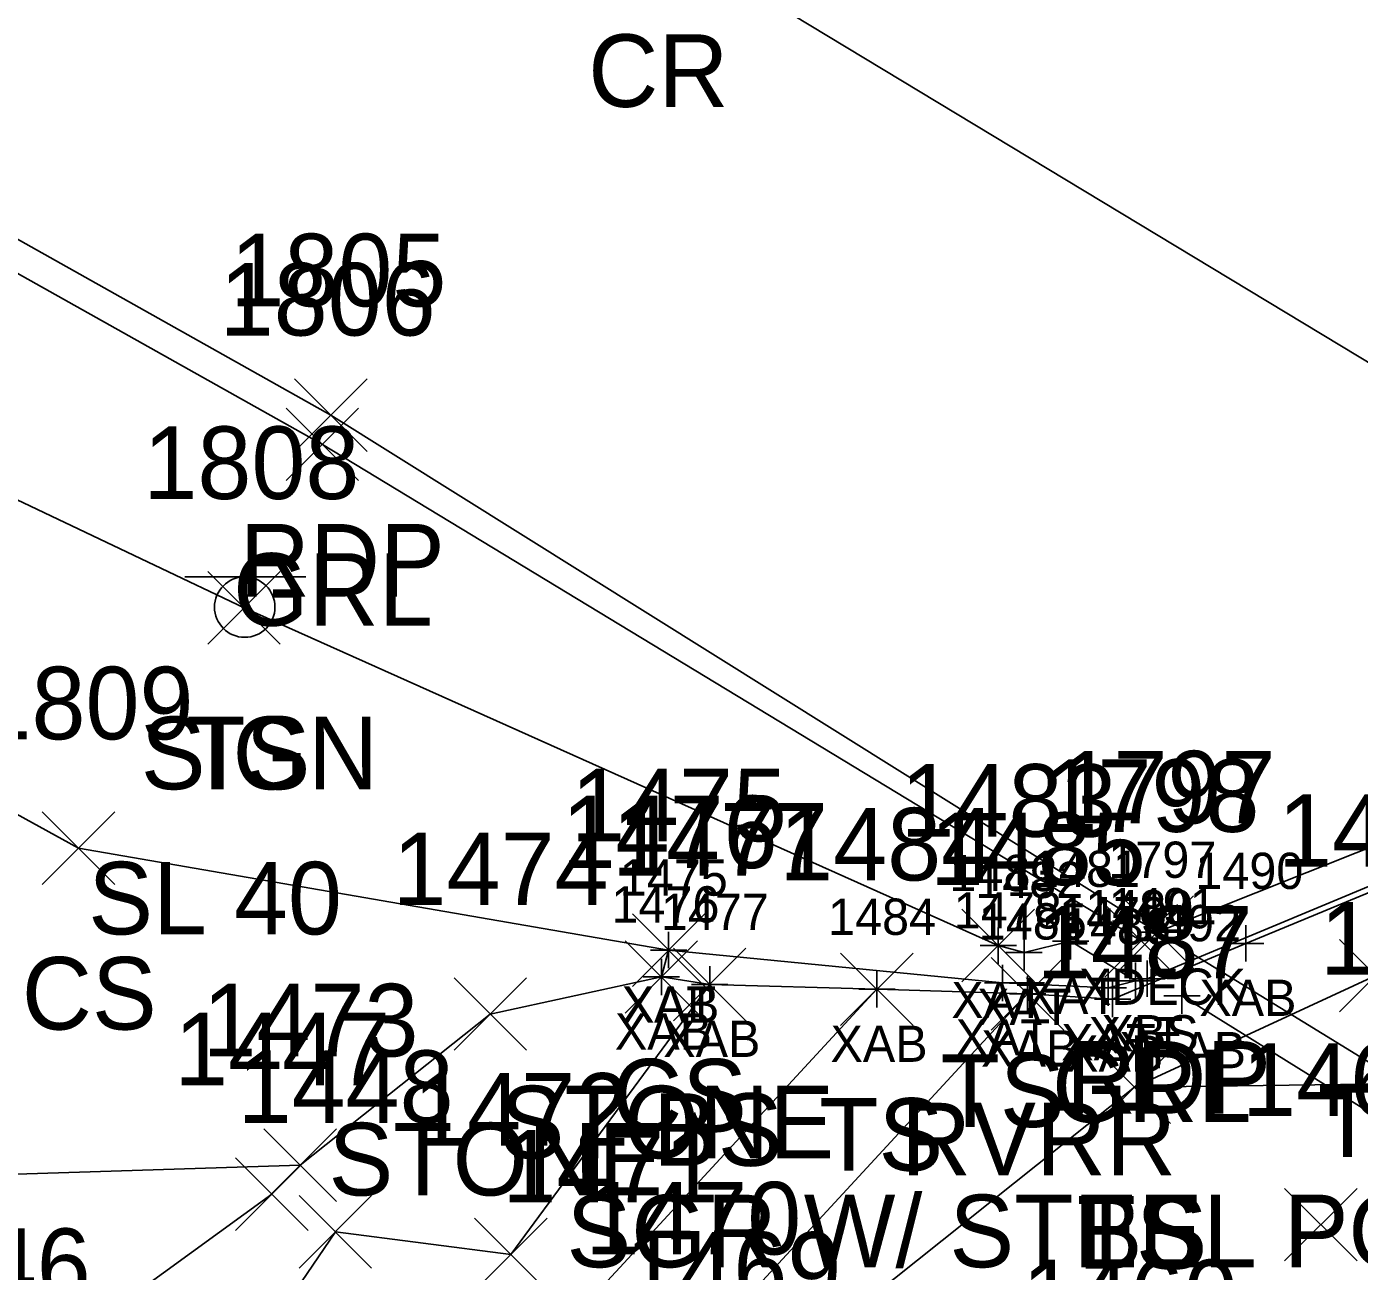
# Model space of a CAD drawing. Extents: x 1537342 to 1542195, y 163002 to 168596.
# Drawn here: x 1541735.99 to 1541772.7, y 163319.29 to 163353.59 of the extents above; entities that cross this region are included whole.
import ezdxf

# ---------------------------------------------------------------- set-up
doc = ezdxf.new("R2010")
doc.units = 0
for name, color, linetype in [('B_A', 7, 'Continuous'), ('B_I', 7, 'Continuous'), ('B_TIC', 7, 'Continuous'), ('BELB', 7, 'Continuous'), ('BF', 7, 'Continuous'), ('BSE', 7, 'Continuous'), ('BSUBM', 7, 'Continuous'), ('L_A', 7, 'Continuous'), ('L_I', 7, 'Continuous'), ('L_TIC', 7, 'Continuous'), ('LASF', 7, 'Continuous'), ('LAWE', 7, 'Continuous'), ('LELB', 7, 'Continuous'), ('P_A', 7, 'Continuous'), ('P_I', 7, 'Continuous'), ('P_TIC', 7, 'Continuous'), ('PET', 7, 'Continuous'), ('PRC', 7, 'Continuous'), ('R_A', 7, 'Continuous'), ('R_C', 7, 'Continuous'), ('R_I', 7, 'Continuous'), ('R_TIC', 7, 'Continuous'), ('RGR', 7, 'Continuous'), ('S_A', 7, 'Continuous'), ('S_C', 7, 'Continuous'), ('S_I', 7, 'Continuous'), ('SSGN', 7, 'Continuous')]:
    doc.layers.add(name, color=color, linetype=linetype)

msp = doc.modelspace()

# ---------------------------------------------------------------- linework, layer by layer
at = {"layer": 'B_TIC'}
for p, q in [((1541764.752, 163328.383), (1541764.827, 163328.383)), ((1541767.139, 163328.632), (1541767.214, 163328.632)), ((1541753.679, 163328.14), (1541753.754, 163328.14)), ((1541753.679, 163328.14), (1541753.754, 163328.14)), ((1541762.761, 163328.265), (1541762.836, 163328.265)), ((1541763.472, 163328.075), (1541763.547, 163328.075)), ((1541769.579, 163328.325), (1541769.655, 163328.325)), ((1541753.478, 163327.4), (1541753.553, 163327.4)), ((1541766.544, 163327.295), (1541766.62, 163327.295)), ((1541766.863, 163327.35), (1541766.938, 163327.35)), ((1541754.81, 163327.195), (1541754.885, 163327.195)), ((1541759.417, 163327.06), (1541759.492, 163327.06)), ((1541762.881, 163327.236), (1541762.956, 163327.236)), ((1541763.568, 163326.932), (1541763.644, 163326.932)), ((1541765.79, 163327.102), (1541765.866, 163327.102)), ((1541765.91, 163326.789), (1541765.986, 163326.789)), ((1541767.822, 163326.884), (1541767.897, 163326.884))]:
    msp.add_line(p, q, dxfattribs=at)
for points in [[(1541767.135, 163328.131), (1541767.135, 163329.132)], [(1541762.757, 163327.765), (1541762.757, 163328.765)], [(1541764.748, 163327.883), (1541764.748, 163328.883)], [(1541769.576, 163327.825), (1541769.576, 163328.825)], [(1541753.675, 163327.64), (1541753.675, 163328.64)], [(1541753.675, 163327.64), (1541753.675, 163328.64)], [(1541763.468, 163327.575), (1541763.468, 163328.575)], [(1541764.248, 163328.383), (1541765.248, 163328.383)], [(1541766.635, 163328.632), (1541767.635, 163328.632)], [(1541753.175, 163328.14), (1541754.175, 163328.14)], [(1541753.175, 163328.14), (1541754.175, 163328.14)], [(1541762.257, 163328.265), (1541763.257, 163328.265)], [(1541762.968, 163328.075), (1541763.968, 163328.075)], [(1541769.076, 163328.325), (1541770.076, 163328.325)], [(1541753.474, 163326.9), (1541753.474, 163327.9)], [(1541754.806, 163326.695), (1541754.806, 163327.695)], [(1541762.877, 163326.736), (1541762.877, 163327.736)], [(1541766.541, 163326.795), (1541766.541, 163327.795)], [(1541766.859, 163326.85), (1541766.859, 163327.85)], [(1541752.974, 163327.4), (1541753.974, 163327.4)], [(1541759.413, 163326.56), (1541759.413, 163327.56)], [(1541763.565, 163326.432), (1541763.565, 163327.432)], [(1541765.787, 163326.602), (1541765.787, 163327.602)], [(1541765.907, 163326.289), (1541765.907, 163327.289)], [(1541766.041, 163327.295), (1541767.041, 163327.295)], [(1541766.359, 163327.35), (1541767.359, 163327.35)], [(1541767.818, 163326.384), (1541767.818, 163327.384)], [(1541754.306, 163327.195), (1541755.306, 163327.195)], [(1541758.913, 163327.06), (1541759.913, 163327.06)], [(1541762.377, 163327.236), (1541763.377, 163327.236)], [(1541763.065, 163326.932), (1541764.065, 163326.932)], [(1541765.287, 163327.102), (1541766.287, 163327.102)], [(1541765.407, 163326.789), (1541766.407, 163326.789)], [(1541767.318, 163326.884), (1541768.318, 163326.884)]]:
    msp.add_lwpolyline(points, dxfattribs=at)
at = {"layer": 'BELB'}
msp.add_lwpolyline([(1541795.579, 163311.161), (1541767.135, 163328.632)], dxfattribs=at)
at = {"layer": 'BF'}
msp.add_lwpolyline([(1541767.818, 163326.884), (1541792.553, 163311.514)], dxfattribs=at)
at = {"layer": 'BSE'}
msp.add_lwpolyline([(1541766.859, 163327.35), (1541784.541, 163334.727), (1541807.069, 163344.219)], dxfattribs=at)
at = {"layer": 'BSUBM'}
for points in [[(1541753.675, 163328.14), (1541753.474, 163327.4), (1541754.806, 163327.195), (1541759.413, 163327.06), (1541763.565, 163326.932), (1541765.907, 163326.789), (1541769.576, 163328.325), (1541782.493, 163333.668), (1541782.581, 163333.735), (1541797.444, 163339.977), (1541807.794, 163344.415), (1541807.593, 163352.289)], [(1541753.675, 163328.14), (1541762.877, 163327.236), (1541765.787, 163327.102), (1541766.541, 163327.295), (1541764.748, 163328.383), (1541763.468, 163328.075), (1541762.757, 163328.265)]]:
    msp.add_lwpolyline(points, dxfattribs=at)
at = {"layer": 'L_TIC'}
for points in [[(1541740.976, 163336.573), (1541742.976, 163338.573)], [(1541742.976, 163336.573), (1541740.976, 163338.573)], [(1541736.414, 163329.95), (1541738.414, 163331.95)], [(1541738.414, 163329.95), (1541736.414, 163331.95)], [(1541752.675, 163327.14), (1541754.675, 163329.14)], [(1541754.675, 163327.14), (1541752.675, 163329.14)], [(1541761.757, 163327.265), (1541763.757, 163329.265)], [(1541763.757, 163327.265), (1541761.757, 163329.265)], [(1541752.474, 163326.4), (1541754.474, 163328.4)], [(1541754.474, 163326.4), (1541752.474, 163328.4)], [(1541772.155, 163326.437), (1541774.155, 163328.437)], [(1541774.155, 163326.437), (1541772.155, 163328.437)], [(1541753.806, 163326.195), (1541755.806, 163328.195)], [(1541755.806, 163326.195), (1541753.806, 163328.195)], [(1541758.413, 163326.06), (1541760.413, 163328.06)], [(1541760.413, 163326.06), (1541758.413, 163328.06)], [(1541762.565, 163325.932), (1541764.565, 163327.932)], [(1541764.565, 163325.932), (1541762.565, 163327.932)], [(1541747.762, 163325.379), (1541749.762, 163327.379)], [(1541749.762, 163325.379), (1541747.762, 163327.379)], [(1541765.506, 163323.36), (1541767.506, 163325.36)], [(1541767.506, 163323.36), (1541765.506, 163325.36)], [(1541765.506, 163323.36), (1541767.506, 163325.36)], [(1541767.506, 163323.36), (1541765.506, 163325.36)], [(1541742.526, 163321.211), (1541744.526, 163323.211)], [(1541744.526, 163321.211), (1541742.526, 163323.211)], [(1541742.526, 163321.211), (1541744.526, 163323.211)], [(1541744.526, 163321.211), (1541742.526, 163323.211)], [(1541741.746, 163320.414), (1541743.746, 163322.414)], [(1541743.746, 163320.414), (1541741.746, 163322.414)], [(1541770.645, 163319.572), (1541772.645, 163321.572)], [(1541772.645, 163319.572), (1541770.645, 163321.572)], [(1541743.492, 163319.375), (1541745.492, 163321.375)], [(1541745.492, 163319.375), (1541743.492, 163321.375)], [(1541748.33, 163318.749), (1541750.33, 163320.749)], [(1541750.33, 163318.749), (1541748.33, 163320.749)]]:
    msp.add_lwpolyline(points, dxfattribs=at)
at = {"layer": 'LASF'}
msp.add_lwpolyline([(1541725.244, 163309.572), (1541734.551, 163315.469), (1541742.746, 163321.414), (1541743.526, 163322.211), (1541748.762, 163326.379), (1541753.474, 163327.4)], dxfattribs=at)
at = {"layer": 'LAWE'}
msp.add_lwpolyline([(1541677.778, 163293.444), (1541698.285, 163296.179), (1541716.759, 163297.211), (1541728.014, 163299.943), (1541740.071, 163305.099), (1541745.426, 163310.811), (1541754.159, 163316.751), (1541763.565, 163326.932)], dxfattribs=at)
at = {"layer": 'LELB'}
for points in [[(1541762.757, 163328.265), (1541741.976, 163337.573), (1541701.303, 163356.937), (1541664.549, 163374.558), (1541614.422, 163401.422), (1541584.182, 163419.261), (1541552.304, 163432.576), (1541546.69, 163431.723)], [(1541753.675, 163328.14), (1541737.414, 163330.95), (1541699.359, 163351.915), (1541657.859, 163368.16), (1541610.377, 163396.928), (1541582.746, 163415.803), (1541550.642, 163428.77), (1541544.422, 163427.2), (1541540.388, 163420.645), (1541544.656, 163416.073), (1541557.529, 163413.194)], [(1541743.526, 163322.211), (1541725.853, 163321.652), (1541695.186, 163341.204), (1541650.611, 163361.066), (1541607.094, 163386.639), (1541578.451, 163407.494), (1541556.53, 163422.329)], [(1541680.476, 163291.861), (1541699.97, 163293.9), (1541717.141, 163294.135), (1541730.523, 163297.571), (1541741.654, 163302.345), (1541748.176, 163305.385), (1541748.078, 163309.08), (1541755.23, 163315.369), (1541766.506, 163324.36), (1541774.317, 163324.466), (1541783.87, 163329.52), (1541794.382, 163332.118), (1541806.545, 163337.396), (1541818.819, 163343.081), (1541839.231, 163350.559), (1541851.311, 163354.645), (1541860.204, 163362.664), (1541879.488, 163366.965), (1541895.128, 163366.199), (1541914.254, 163372.826), (1541910.846, 163375.465), (1541893.701, 163387.218), (1541872.662, 163402.005), (1541849.049, 163411.834)], [(1541766.506, 163324.36), (1541773.155, 163327.437), (1541783.027, 163332.327)], [(1541724.974, 163304.042), (1541731.669, 163304.713), (1541739.882, 163307.368), (1541744.733, 163312.178), (1541751.219, 163318.185), (1541759.413, 163327.06)], [(1541731.669, 163304.713), (1541739.13, 163312.48), (1541744.492, 163320.375), (1541749.33, 163319.749), (1541754.806, 163327.195)]]:
    msp.add_lwpolyline(points, dxfattribs=at)
at = {"layer": 'P_TIC'}
for points in [[(1541743.371, 163341.884), (1541745.371, 163343.884)], [(1541745.371, 163341.884), (1541743.371, 163343.884)], [(1541766.135, 163327.632), (1541768.135, 163329.632)], [(1541768.135, 163327.632), (1541766.135, 163329.632)]]:
    msp.add_lwpolyline(points, dxfattribs=at)
at = {"layer": 'PET'}
msp.add_lwpolyline([(1541804.882, 163343.94), (1541786.304, 163336.277), (1541767.135, 163328.632), (1541744.371, 163342.884), (1541704.795, 163365.128), (1541670.451, 163382.893), (1541617.103, 163408.356), (1541585.571, 163422.3), (1541550.232, 163436.7), (1541542.2, 163439.813)], dxfattribs=at)
at = {"layer": 'PRC'}
msp.add_lwpolyline([(1541786.304, 163336.277), (1541753.026, 163356.379), (1541711.826, 163379.06), (1541677.625, 163397.186), (1541623.384, 163422.529), (1541592.115, 163436.736), (1541548.189, 163454.577)], dxfattribs=at)
at = {"layer": 'R_TIC'}
for points in [[(1541743.134, 163341.079), (1541745.134, 163343.079)], [(1541745.134, 163341.079), (1541743.134, 163343.079)], [(1541765.695, 163327.399), (1541767.695, 163329.399)], [(1541767.695, 163327.399), (1541765.695, 163329.399)]]:
    msp.add_lwpolyline(points, dxfattribs=at)
at = {"layer": 'RGR'}
msp.add_lwpolyline([(1541766.695, 163328.399), (1541744.134, 163342.079), (1541704.307, 163364.433), (1541668.885, 163380.952)], dxfattribs=at)
at = {"layer": 'SSGN'}
for p, q in [((1541740.349, 163338.427), (1541743.682, 163338.427)), ((1541741.996, 163337.594), (1541741.996, 163337.594))]:
    msp.add_line(p, q, dxfattribs=at)
msp.add_circle((1541741.996, 163337.594), 0.833, dxfattribs=at)

# ---------------------------------------------------------------- texts
at = {"layer": 'B_A'}
for s, p in [('XDECK', (1541764.978, 163326.632)), ('XAT', (1541763.453, 163326.383)), ('XAB', (1541768.296, 163326.325)), ('XAT', (1541752.38, 163326.14)), ('XAB', (1541752.396, 163326.14)), ('XAT', (1541761.462, 163326.265)), ('XAT', (1541762.173, 163326.075)), ('XAB', (1541752.195, 163325.4)), ('XAB', (1541753.527, 163325.195)), ('XAT', (1541761.582, 163325.236)), ('XAT', (1541765.245, 163325.295)), ('XBS', (1541765.599, 163325.35)), ('XAB', (1541758.134, 163325.06)), ('XAB', (1541762.285, 163324.932)), ('XAT', (1541764.492, 163325.102)), ('XFAB', (1541766.09, 163324.884)), ('XAB', (1541764.627, 163324.789))]:
    msp.add_text(s, height=1, dxfattribs=at).set_placement(p)
at = {"layer": 'B_I'}
for s, p in [('1797', (1541765.789, 163330.132)), ('1475', (1541752.329, 163329.64)), ('1475', (1541752.329, 163329.64)), ('1483', (1541761.411, 163329.765)), ('1482', (1541762.122, 163329.575)), ('1481', (1541763.686, 163329.883)), ('1490', (1541768.186, 163329.825)), ('1476', (1541752.1, 163328.9)), ('1491', (1541765.796, 163328.85)), ('1477', (1541753.46, 163328.695)), ('1484', (1541758.067, 163328.56)), ('1478', (1541761.531, 163328.736)), ('1479', (1541764.437, 163328.602)), ('1480', (1541765.151, 163328.795)), ('1485', (1541762.218, 163328.432)), ('1486', (1541764.533, 163328.289)), ('1492', (1541766.472, 163328.384))]:
    msp.add_text(s, height=1, dxfattribs=at).set_placement(p)
at = {"layer": 'L_A'}
for s, p in [('TS', (1541740.386, 163332.573)), ('CS', (1541735.855, 163325.95)), ('CS', (1541752.116, 163323.14)), ('TS', (1541761.167, 163323.265)), ('STONE', (1541749.018, 163322.4)), ('TS', (1541771.564, 163322.437)), ('BS', (1541753.247, 163322.195)), ('TS', (1541757.823, 163322.06)), ('RVRR', (1541760.077, 163321.932)), ('STONE', (1541744.305, 163321.379)), ('TS', (1541764.916, 163319.36)), ('BS', (1541764.947, 163319.36))]:
    msp.add_text(s, height=2, dxfattribs=at).set_placement(p)
at = {"layer": 'L_I'}
for s, p in [('1808', (1541739.205, 163340.573)), ('1809', (1541734.634, 163333.95)), ('1483', (1541760.065, 163331.265)), ('1475', (1541750.983, 163331.14)), ('1476', (1541750.726, 163330.4)), ('1488', (1541770.462, 163330.437)), ('1477', (1541752.113, 163330.195)), ('1484', (1541756.721, 163330.06)), ('1485', (1541760.872, 163329.932)), ('1474', (1541746.069, 163329.379)), ('1489', (1541771.616, 163327.466)), ('1487', (1541763.813, 163327.36)), ('1487', (1541763.813, 163327.36)), ('1473', (1541740.833, 163325.211)), ('1473', (1541740.833, 163325.211)), ('1447', (1541740.053, 163324.414)), ('1461', (1541769.472, 163323.572)), ('1448', (1541741.8, 163323.375)), ('1472', (1541746.637, 163322.749)), ('1471', (1541749.094, 163321.185)), ('1470', (1541751.38, 163319.751)), ('1446', (1541731.803, 163318.469)), ('1469', (1541752.482, 163318.369)), ('1460', (1541763.407, 163317.606))]:
    msp.add_text(s, height=2, dxfattribs=at).set_placement(p)
at = {"layer": 'P_A'}
for s, p in [('CR', (1541751.459, 163351.379)), ('RDP', (1541741.859, 163337.884)), ('RDP', (1541764.624, 163323.632))]:
    msp.add_text(s, height=2, dxfattribs=at).set_placement(p)
at = {"layer": 'P_I'}
for s, p in [('1805', (1541741.6, 163345.884)), ('1797', (1541764.443, 163331.632))]:
    msp.add_text(s, height=2, dxfattribs=at).set_placement(p)
at = {"layer": 'R_A'}
for p in [(1541741.677, 163337.079), (1541764.238, 163323.399)]:
    msp.add_text('GRL', height=2, dxfattribs=at).set_placement(p)
at = {"layer": 'R_C'}
msp.add_text('SGR W/ STEEL POST', height=2, dxfattribs=at).set_placement((1541750.86, 163319.399))
at = {"layer": 'R_I'}
for s, p in [('1806', (1541741.307, 163345.079)), ('1798', (1541764.002, 163331.399))]:
    msp.add_text(s, height=2, dxfattribs=at).set_placement(p)
at = {"layer": 'S_A'}
msp.add_text('SIGN', height=2, dxfattribs=at).set_placement((1541739.134, 163332.573))
at = {"layer": 'S_C'}
msp.add_text('SL 40', height=2, dxfattribs=at).set_placement((1541737.685, 163328.573))
at = {"layer": 'S_I'}
msp.add_text('1808', height=2, dxfattribs=at).set_placement((1541739.205, 163340.573))

doc.saveas('drawing.dxf')
